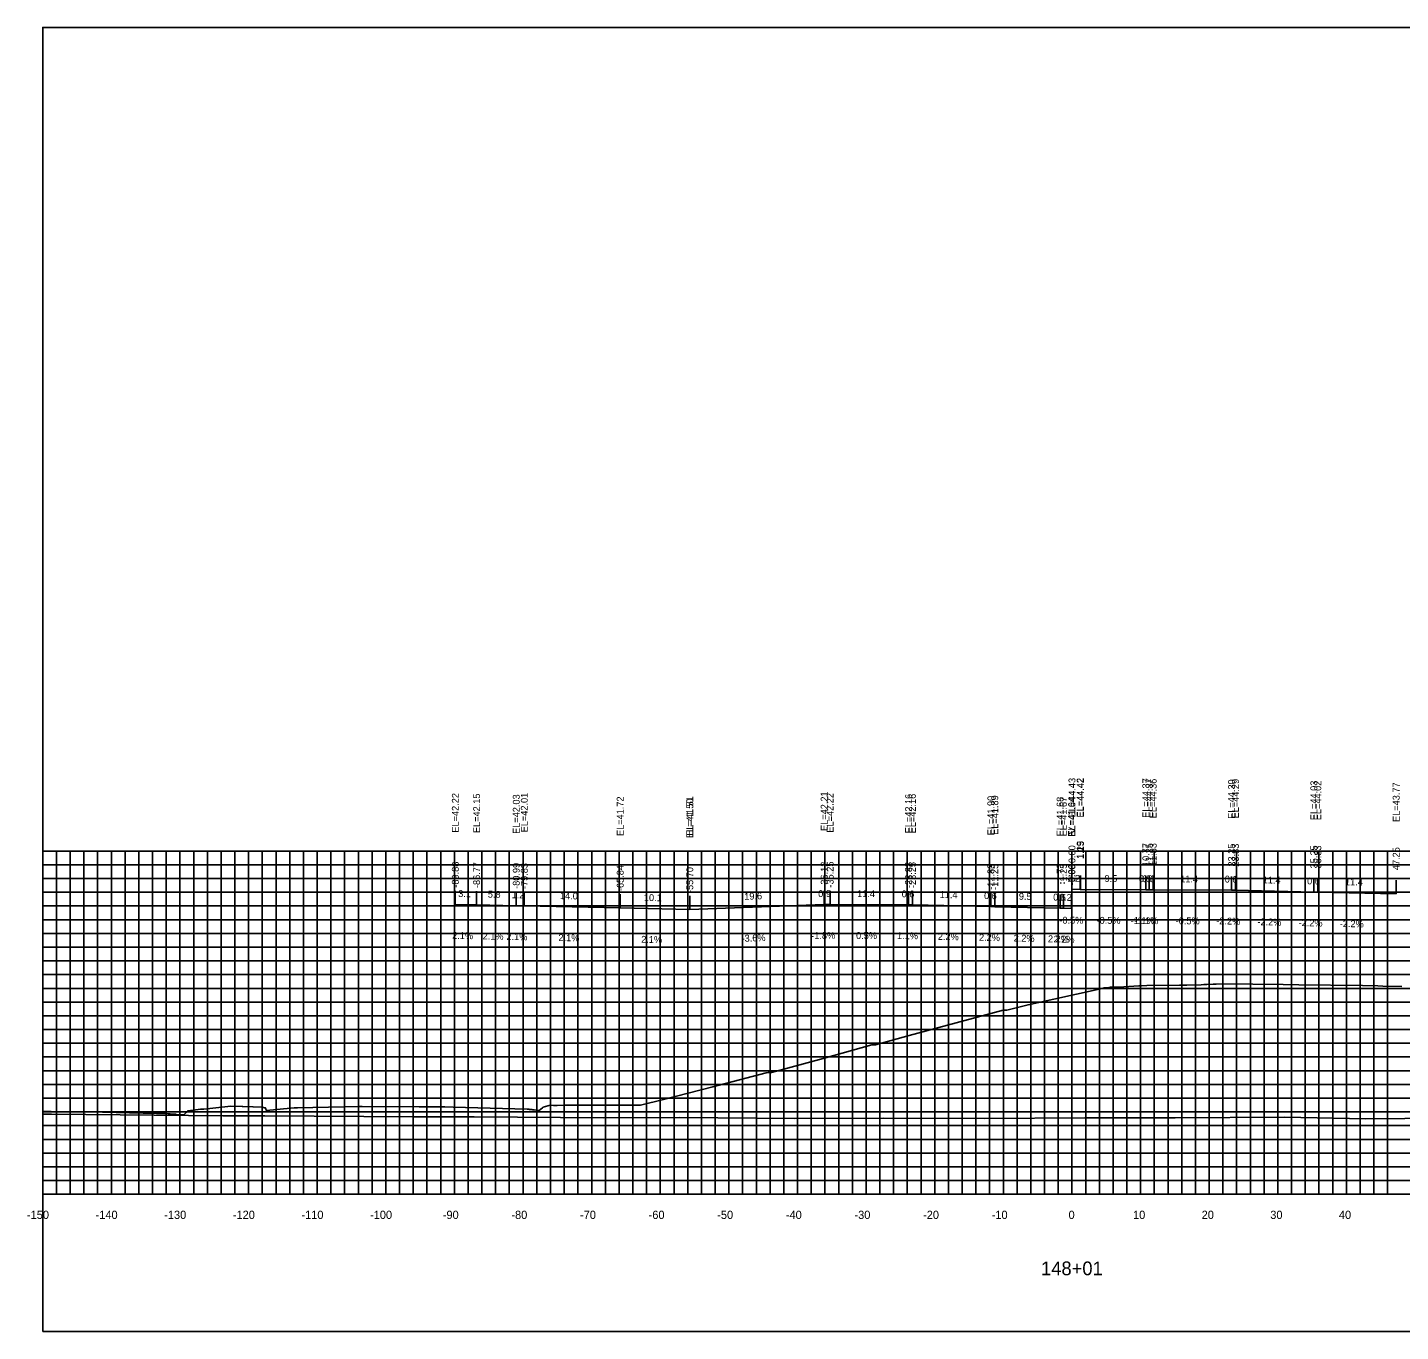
# Model space of a CAD drawing. Extents: x 1800880 to 1818864, y 245271 to 250560.
# Drawn here: x 1808044.3 to 1808244.4, y 246963.3 to 247153.3 of the extents above; entities that cross this region are included whole.
import ezdxf

# ---------------------------------------------------------------- set-up
doc = ezdxf.new("R2010")
doc.units = 0
for name, color, linetype in [('ANNO-TXT', 7, 'Continuous'), ('AXIS', 7, 'Continuous'), ('CL-CNST', 7, 'Continuous'), ('DESIGN - DRAINAGE - Bridges', 7, 'Continuous'), ('Level 32', 7, 'Continuous'), ('Level 37', 7, 'Continuous'), ('Level 46', 7, 'Continuous'), ('Level 62', 7, 'Continuous'), ('SHT-BDR', 7, 'Continuous')]:
    doc.layers.add(name, color=color, linetype=linetype)

msp = doc.modelspace()

# ---------------------------------------------------------------- linework, layer by layer
at = {"layer": 'AXIS'}
msp.add_lwpolyline([(1808196.5, 247027.72), (1808197.69, 247027.71), (1808197.75, 247027.71), (1808207.27, 247027.66), (1808207.75, 247027.65), (1808208.33, 247027.65), (1808219.75, 247027.59), (1808220.33, 247027.57), (1808231.75, 247027.32), (1808232.33, 247027.31), (1808243.75, 247027.06)], dxfattribs=at)
at = {"layer": 'CL-CNST'}
msp.add_lwpolyline([(1808046.5, 246995.34), (1808047.74, 246995.35), (1808051.34, 246995.31), (1808055.2, 246995.26), (1808063.09, 246995.07), (1808063.44, 246995.06), (1808063.82, 246995.05), (1808064.24, 246995.04), (1808064.32, 246995.03), (1808064.4, 246995.03), (1808064.78, 246995), (1808065.07, 246994.99), (1808065.29, 246994.97), (1808065.47, 246994.96), (1808065.61, 246994.95), (1808065.73, 246994.94), (1808065.84, 246994.94), (1808065.92, 246994.93), (1808067.06, 246994.86), (1808067.47, 246995.25), (1808067.6, 246995.35), (1808067.64, 246995.44), (1808067.68, 246995.44), (1808069.47, 246995.69), (1808069.83, 246995.69), (1808070, 246995.69), (1808073.91, 246996.12), (1808075.57, 246996.06), (1808075.66, 246996.06), (1808077.14, 246996.03), (1808077.18, 246996.02), (1808078.55, 246995.97), (1808078.65, 246995.92), (1808078.65, 246995.92), (1808078.66, 246995.92), (1808078.67, 246995.92), (1808078.67, 246995.92), (1808078.68, 246995.92), (1808078.69, 246995.92), (1808078.7, 246995.91), (1808078.71, 246995.91), (1808078.73, 246995.91), (1808078.74, 246995.91), (1808078.76, 246995.9), (1808078.78, 246995.9), (1808078.81, 246995.89), (1808078.84, 246995.89), (1808078.88, 246995.88), (1808078.92, 246995.87), (1808078.97, 246995.86), (1808078.98, 246995.83), (1808078.99, 246995.79), (1808078.99, 246995.76), (1808079, 246995.73), (1808079, 246995.71), (1808079.01, 246995.7), (1808079.1, 246995.51), (1808082.62, 246995.82), (1808082.67, 246995.83), (1808083.12, 246995.89), (1808083.32, 246995.89), (1808083.63, 246995.89), (1808090.37, 246996.02), (1808092.57, 246996.06), (1808093.05, 246996.06), (1808101.37, 246996.03), (1808105.09, 246996.02), (1808106.31, 246995.99), (1808117.1, 246995.7), (1808117.18, 246995.69), (1808117.33, 246995.67), (1808117.46, 246995.66), (1808117.57, 246995.64), (1808117.66, 246995.63), (1808117.74, 246995.63), (1808117.81, 246995.62), (1808117.87, 246995.61), (1808117.92, 246995.61), (1808117.97, 246995.6), (1808118.02, 246995.6), (1808118.06, 246995.59), (1808118.1, 246995.59), (1808118.14, 246995.59), (1808118.85, 246995.51), (1808119.31, 246995.88), (1808119.45, 246995.98), (1808120.43, 246996.25), (1808120.46, 246996.25), (1808120.51, 246996.25), (1808120.95, 246996.24), (1808121.46, 246996.24), (1808122.39, 246996.27), (1808133.1, 246996.28), (1808133.41, 246996.28), (1808133.6, 246996.28), (1808136.99, 246997.11), (1808144.15, 246998.95), (1808151.93, 247000.96), (1808152.25, 247001.03), (1808152.37, 247001.02), (1808152.69, 247001.01), (1808160.25, 247003.09), (1808167.35, 247005.05), (1808167.72, 247005.05), (1808167.85, 247005.05), (1808172.79, 247006.44), (1808186.45, 247010.09), (1808186.62, 247010.1), (1808187.03, 247010.11), (1808190.1, 247010.89), (1808200.88, 247013.28), (1808201.18, 247013.37), (1808201.87, 247013.42), (1808201.97, 247013.43), (1808202.13, 247013.44), (1808202.52, 247013.44), (1808202.76, 247013.45), (1808203.34, 247013.48), (1808206.24, 247013.64), (1808206.65, 247013.66), (1808207.42, 247013.71), (1808212.16, 247013.75), (1808213.22, 247013.76), (1808215.34, 247013.81), (1808215.74, 247013.83), (1808216.14, 247013.83), (1808217.07, 247013.89), (1808217.53, 247013.91), (1808218.42, 247013.96), (1808227.3, 247013.84), (1808229.55, 247013.81), (1808238.82, 247013.68), (1808241.09, 247013.65), (1808241.82, 247013.63), (1808244.59, 247013.56)], dxfattribs=at)
at = {"layer": 'DESIGN - DRAINAGE - Bridges'}
for p, q in [((1808046.44, 247033.29), (1808046.5, 247033.29)), ((1808046.5, 246983.29), (1808046.5, 247033.29)), ((1808046.44, 247023.29), (1808046.5, 247023.29)), ((1808046.44, 247013.29), (1808046.5, 247013.29)), ((1808046.44, 247003.29), (1808046.5, 247003.29)), ((1808046.44, 246993.29), (1808046.5, 246993.29)), ((1808046.44, 246983.29), (1808046.5, 246983.29)), ((1808046.5, 246983.29), (1808346.5, 246983.29)), ((1808046.5, 246983.23), (1808046.5, 246983.29)), ((1808056.5, 246983.23), (1808056.5, 246983.29)), ((1808066.5, 246983.23), (1808066.5, 246983.29)), ((1808076.5, 246983.23), (1808076.5, 246983.29)), ((1808086.5, 246983.23), (1808086.5, 246983.29)), ((1808096.5, 246983.23), (1808096.5, 246983.29)), ((1808106.5, 246983.23), (1808106.5, 246983.29)), ((1808116.5, 246983.23), (1808116.5, 246983.29)), ((1808126.5, 246983.23), (1808126.5, 246983.29)), ((1808136.5, 246983.23), (1808136.5, 246983.29)), ((1808146.5, 246983.23), (1808146.5, 246983.29)), ((1808156.5, 246983.23), (1808156.5, 246983.29)), ((1808166.5, 246983.23), (1808166.5, 246983.29)), ((1808176.5, 246983.23), (1808176.5, 246983.29)), ((1808186.5, 246983.23), (1808186.5, 246983.29)), ((1808196.5, 246983.23), (1808196.5, 246983.29)), ((1808206.5, 246983.23), (1808206.5, 246983.29)), ((1808216.5, 246983.23), (1808216.5, 246983.29)), ((1808226.5, 246983.23), (1808226.5, 246983.29)), ((1808236.5, 246983.23), (1808236.5, 246983.29))]:
    msp.add_line(p, q, dxfattribs=at)
at = {"layer": 'Level 37'}
for p, q in [((1808196.5, 247027.72), (1808196.5, 247029.72)), ((1808197.69, 247027.71), (1808197.69, 247029.71)), ((1808197.75, 247027.71), (1808197.75, 247029.71)), ((1808207.27, 247027.66), (1808207.27, 247029.66)), ((1808207.75, 247027.65), (1808207.75, 247029.65)), ((1808208.33, 247027.65), (1808208.33, 247029.65)), ((1808219.75, 247027.59), (1808219.75, 247029.59)), ((1808220.33, 247027.57), (1808220.33, 247029.57)), ((1808231.75, 247027.32), (1808231.75, 247029.32)), ((1808232.33, 247027.31), (1808232.33, 247029.31)), ((1808243.75, 247027.06), (1808243.75, 247029.06)), ((1808106.63, 247025.5), (1808106.63, 247027.5)), ((1808109.73, 247025.44), (1808109.73, 247027.44)), ((1808115.51, 247025.32), (1808115.51, 247027.32)), ((1808116.68, 247025.29), (1808116.68, 247027.29)), ((1808130.66, 247025), (1808130.66, 247027)), ((1808140.8, 247024.79), (1808140.8, 247026.79)), ((1808140.8, 247024.79), (1808140.8, 247026.79)), ((1808160.39, 247025.49), (1808160.39, 247027.49)), ((1808161.25, 247025.51), (1808161.25, 247027.51)), ((1808172.68, 247025.45), (1808172.68, 247027.45)), ((1808173.25, 247025.44), (1808173.25, 247027.44)), ((1808184.68, 247025.19), (1808184.68, 247027.19)), ((1808185.25, 247025.18), (1808185.25, 247027.18)), ((1808194.77, 247024.97), (1808194.77, 247026.97)), ((1808195.25, 247024.96), (1808195.25, 247026.96)), ((1808196.44, 247024.93), (1808196.44, 247026.93)), ((1808196.5, 247024.93), (1808196.5, 247026.93))]:
    msp.add_line(p, q, dxfattribs=at)
msp.add_lwpolyline([(1808046.5, 246963.29), (1808346.5, 246963.29), (1808346.5, 247153.29), (1808046.5, 247153.29)], close=True, dxfattribs=at)
at = {"layer": 'Level 46'}
for p, q in [((1808046.5, 247033.29), (1808346.5, 247033.29)), ((1808046.5, 246983.29), (1808046.5, 247033.29)), ((1808048.5, 246983.29), (1808048.5, 247033.29)), ((1808050.5, 246983.29), (1808050.5, 247033.29)), ((1808052.5, 246983.29), (1808052.5, 247033.29)), ((1808054.5, 246983.29), (1808054.5, 247033.29)), ((1808056.5, 246983.29), (1808056.5, 247033.29)), ((1808058.5, 246983.29), (1808058.5, 247033.29)), ((1808060.5, 246983.29), (1808060.5, 247033.29)), ((1808062.5, 246983.29), (1808062.5, 247033.29)), ((1808064.5, 246983.29), (1808064.5, 247033.29)), ((1808066.5, 246983.29), (1808066.5, 247033.29)), ((1808068.5, 246983.29), (1808068.5, 247033.29)), ((1808070.5, 246983.29), (1808070.5, 247033.29)), ((1808072.5, 246983.29), (1808072.5, 247033.29)), ((1808074.5, 246983.29), (1808074.5, 247033.29)), ((1808076.5, 246983.29), (1808076.5, 247033.29)), ((1808078.5, 246983.29), (1808078.5, 247033.29)), ((1808080.5, 246983.29), (1808080.5, 247033.29)), ((1808082.5, 246983.29), (1808082.5, 247033.29)), ((1808084.5, 246983.29), (1808084.5, 247033.29)), ((1808086.5, 246983.29), (1808086.5, 247033.29)), ((1808088.5, 246983.29), (1808088.5, 247033.29)), ((1808090.5, 246983.29), (1808090.5, 247033.29)), ((1808092.5, 246983.29), (1808092.5, 247033.29)), ((1808094.5, 246983.29), (1808094.5, 247033.29)), ((1808096.5, 246983.29), (1808096.5, 247033.29)), ((1808098.5, 246983.29), (1808098.5, 247033.29)), ((1808100.5, 246983.29), (1808100.5, 247033.29)), ((1808102.5, 246983.29), (1808102.5, 247033.29)), ((1808104.5, 246983.29), (1808104.5, 247033.29)), ((1808106.5, 246983.29), (1808106.5, 247033.29)), ((1808108.5, 246983.29), (1808108.5, 247033.29)), ((1808110.5, 246983.29), (1808110.5, 247033.29)), ((1808112.5, 246983.29), (1808112.5, 247033.29)), ((1808114.5, 246983.29), (1808114.5, 247033.29)), ((1808116.5, 246983.29), (1808116.5, 247033.29)), ((1808118.5, 246983.29), (1808118.5, 247033.29)), ((1808120.5, 246983.29), (1808120.5, 247033.29)), ((1808122.5, 246983.29), (1808122.5, 247033.29)), ((1808124.5, 246983.29), (1808124.5, 247033.29)), ((1808126.5, 246983.29), (1808126.5, 247033.29)), ((1808128.5, 246983.29), (1808128.5, 247033.29)), ((1808130.5, 246983.29), (1808130.5, 247033.29)), ((1808132.5, 246983.29), (1808132.5, 247033.29)), ((1808134.5, 246983.29), (1808134.5, 247033.29)), ((1808136.5, 246983.29), (1808136.5, 247033.29)), ((1808138.5, 246983.29), (1808138.5, 247033.29)), ((1808140.5, 246983.29), (1808140.5, 247033.29)), ((1808142.5, 246983.29), (1808142.5, 247033.29)), ((1808144.5, 246983.29), (1808144.5, 247033.29)), ((1808146.5, 246983.29), (1808146.5, 247033.29)), ((1808148.5, 246983.29), (1808148.5, 247033.29)), ((1808150.5, 246983.29), (1808150.5, 247033.29)), ((1808152.5, 246983.29), (1808152.5, 247033.29)), ((1808154.5, 246983.29), (1808154.5, 247033.29)), ((1808156.5, 246983.29), (1808156.5, 247033.29)), ((1808158.5, 246983.29), (1808158.5, 247033.29)), ((1808160.5, 246983.29), (1808160.5, 247033.29)), ((1808162.5, 246983.29), (1808162.5, 247033.29)), ((1808164.5, 246983.29), (1808164.5, 247033.29)), ((1808166.5, 246983.29), (1808166.5, 247033.29)), ((1808168.5, 246983.29), (1808168.5, 247033.29)), ((1808170.5, 246983.29), (1808170.5, 247033.29)), ((1808172.5, 246983.29), (1808172.5, 247033.29)), ((1808174.5, 246983.29), (1808174.5, 247033.29)), ((1808176.5, 246983.29), (1808176.5, 247033.29)), ((1808178.5, 246983.29), (1808178.5, 247033.29)), ((1808180.5, 246983.29), (1808180.5, 247033.29)), ((1808182.5, 246983.29), (1808182.5, 247033.29)), ((1808184.5, 246983.29), (1808184.5, 247033.29)), ((1808186.5, 246983.29), (1808186.5, 247033.29)), ((1808188.5, 246983.29), (1808188.5, 247033.29)), ((1808190.5, 246983.29), (1808190.5, 247033.29)), ((1808192.5, 246983.29), (1808192.5, 247033.29)), ((1808194.5, 246983.29), (1808194.5, 247033.29)), ((1808196.5, 246983.29), (1808196.5, 247033.29)), ((1808198.5, 246983.29), (1808198.5, 247033.29)), ((1808200.5, 246983.29), (1808200.5, 247033.29)), ((1808202.5, 246983.29), (1808202.5, 247033.29)), ((1808204.5, 246983.29), (1808204.5, 247033.29)), ((1808206.5, 246983.29), (1808206.5, 247033.29)), ((1808208.5, 246983.29), (1808208.5, 247033.29)), ((1808210.5, 246983.29), (1808210.5, 247033.29)), ((1808212.5, 246983.29), (1808212.5, 247033.29)), ((1808214.5, 246983.29), (1808214.5, 247033.29)), ((1808216.5, 246983.29), (1808216.5, 247033.29)), ((1808218.5, 246983.29), (1808218.5, 247033.29)), ((1808220.5, 246983.29), (1808220.5, 247033.29)), ((1808222.5, 246983.29), (1808222.5, 247033.29)), ((1808224.5, 246983.29), (1808224.5, 247033.29)), ((1808226.5, 246983.29), (1808226.5, 247033.29)), ((1808228.5, 246983.29), (1808228.5, 247033.29)), ((1808230.5, 246983.29), (1808230.5, 247033.29)), ((1808232.5, 246983.29), (1808232.5, 247033.29)), ((1808234.5, 246983.29), (1808234.5, 247033.29)), ((1808236.5, 246983.29), (1808236.5, 247033.29)), ((1808238.5, 246983.29), (1808238.5, 247033.29)), ((1808240.5, 246983.29), (1808240.5, 247033.29)), ((1808242.5, 246983.29), (1808242.5, 247033.29)), ((1808046.5, 247031.29), (1808346.5, 247031.29)), ((1808046.5, 247029.29), (1808346.5, 247029.29)), ((1808046.5, 247027.29), (1808346.5, 247027.29)), ((1808046.5, 247025.29), (1808346.5, 247025.29)), ((1808046.5, 247023.29), (1808346.5, 247023.29)), ((1808046.5, 247021.29), (1808346.5, 247021.29)), ((1808046.5, 247019.29), (1808346.5, 247019.29)), ((1808046.5, 247017.29), (1808346.5, 247017.29)), ((1808046.5, 247015.29), (1808346.5, 247015.29)), ((1808046.5, 247013.29), (1808346.5, 247013.29)), ((1808046.5, 247011.29), (1808346.5, 247011.29)), ((1808046.5, 247009.29), (1808346.5, 247009.29)), ((1808046.5, 247007.29), (1808346.5, 247007.29)), ((1808046.5, 247005.29), (1808346.5, 247005.29)), ((1808046.5, 247003.29), (1808346.5, 247003.29)), ((1808046.5, 247001.29), (1808346.5, 247001.29)), ((1808046.5, 246999.29), (1808346.5, 246999.29)), ((1808046.5, 246997.29), (1808346.5, 246997.29)), ((1808046.5, 246995.29), (1808346.5, 246995.29)), ((1808046.5, 246993.29), (1808346.5, 246993.29)), ((1808046.5, 246991.29), (1808346.5, 246991.29)), ((1808046.5, 246989.29), (1808346.5, 246989.29)), ((1808046.5, 246987.29), (1808346.5, 246987.29)), ((1808046.5, 246985.29), (1808346.5, 246985.29)), ((1808046.5, 246983.29), (1808346.5, 246983.29))]:
    msp.add_line(p, q, dxfattribs=at)
at = {"layer": 'Level 62'}
for points in [[(1808106.63, 247025.5), (1808109.73, 247025.44), (1808115.51, 247025.32), (1808116.68, 247025.29), (1808130.66, 247025), (1808140.8, 247024.79)], [(1808140.8, 247024.79), (1808160.39, 247025.49), (1808161.25, 247025.51), (1808172.68, 247025.45), (1808173.25, 247025.44), (1808184.68, 247025.19), (1808185.25, 247025.18), (1808194.77, 247024.97), (1808195.25, 247024.96), (1808196.44, 247024.93), (1808196.5, 247024.93)], [(1808046.5, 246994.96), (1808047.77, 246994.95), (1808072.75, 246994.72), (1808078.89, 246994.71), (1808100.5, 246994.57), (1808109.36, 246994.57), (1808128.26, 246994.44), (1808139.37, 246994.45), (1808156.02, 246994.34), (1808169.02, 246994.38), (1808183.77, 246994.33), (1808198.39, 246994.4), (1808211.53, 246994.42), (1808227.54, 246994.51), (1808239.28, 246994.3), (1808256.52, 246994.4), (1808267.04, 246994.52), (1808276.74, 246994.45), (1808294.79, 246994.56), (1808304.21, 246994.72), (1808322.55, 246994.83), (1808331.64, 246994.58), (1808346.5, 246994.68)]]:
    msp.add_lwpolyline(points, dxfattribs=at)

# ---------------------------------------------------------------- texts
for s, p in [('-150', (1808044.2, 246979.69)), ('-140', (1808054.2, 246979.69)), ('-130', (1808064.2, 246979.69)), ('-120', (1808074.2, 246979.69)), ('-110', (1808084.2, 246979.69)), ('-100', (1808094.2, 246979.69)), ('-90', (1808104.8, 246979.69)), ('-80', (1808114.8, 246979.69)), ('-70', (1808124.8, 246979.69)), ('-60', (1808134.8, 246979.69)), ('-50', (1808144.8, 246979.69)), ('-40', (1808154.8, 246979.69)), ('-30', (1808164.8, 246979.69)), ('-20', (1808174.8, 246979.69)), ('-10', (1808184.8, 246979.69)), ('0', (1808196, 246979.69)), ('10', (1808205.4, 246979.69)), ('20', (1808215.4, 246979.69)), ('30', (1808225.4, 246979.69)), ('40', (1808235.4, 246979.69))]:
    msp.add_text(s, height=1.2).set_placement(p)
at = {"layer": 'ANNO-TXT'}
for s, rotation, p in [('1.2', 359.6981, (1808195.82, 247028.82)), ('9.5', 359.6981, (1808201.24, 247028.79)), ('0.5', 359.3576, (1808206.24, 247028.77)), ('0.6', 359.3576, (1808206.75, 247028.76)), ('11.4', 359.6981, (1808212.27, 247028.73)), ('0.6', 358.7397, (1808218.76, 247028.71)), ('11.4', 358.7397, (1808224.29, 247028.59)), ('0.6', 358.7397, (1808230.76, 247028.44)), ('11.4', 358.7397, (1808236.29, 247028.32)), ('3.1', 358.8131, (1808107.04, 247026.6)), ('5.8', 358.8087, (1808111.36, 247026.51)), ('1.2', 358.8087, (1808114.83, 247026.43)), ('14.0', 358.8087, (1808121.87, 247026.29)), ('10.1', 358.8087, (1808134.1, 247026.03)), ('19.6', 2.0532, (1808148.75, 247026.18)), ('0.9', 1.0364, (1808159.52, 247026.58)), ('11.4', 359.6981, (1808165.19, 247026.59)), ('0.6', 359.3576, (1808171.67, 247026.56)), ('11.4', 358.7397, (1808177.21, 247026.46)), ('0.6', 358.7397, (1808183.68, 247026.31)), ('9.5', 358.7397, (1808188.75, 247026.2)), ('0.5', 358.7397, (1808193.75, 247026.09)), ('1.2', 358.7397, (1808194.59, 247026.07)), ('-0.5%', 359.6981, (1808194.66, 247022.72)), ('-0.5%', 359.6981, (1808200.08, 247022.7)), ('-1.1%', 359.3576, (1808205.05, 247022.68)), ('-1.1%', 359.3576, (1808205.58, 247022.68)), ('-0.5%', 359.6981, (1808211.61, 247022.63)), ('-2.2%', 358.7397, (1808217.52, 247022.63)), ('-2.2%', 358.7397, (1808223.52, 247022.5)), ('-2.2%', 358.7397, (1808229.52, 247022.37)), ('-2.2%', 358.7397, (1808235.52, 247022.24)), ('2.1%', 358.8131, (1808106.16, 247020.51)), ('2.1%', 358.8087, (1808110.6, 247020.42)), ('2.1%', 358.8087, (1808114.08, 247020.35)), ('2.1%', 358.8087, (1808121.65, 247020.19)), ('2.1%', 358.8087, (1808133.71, 247019.94)), ('-3.6%', 2.0532, (1808148.36, 247020.06)), ('-1.8%', 1.0364, (1808158.5, 247020.46)), ('0.5%', 359.6981, (1808165.03, 247020.49)), ('1.1%', 359.3576, (1808171, 247020.47)), ('2.2%', 358.7397, (1808176.94, 247020.36)), ('2.2%', 358.7397, (1808182.94, 247020.23)), ('2.2%', 358.7397, (1808187.99, 247020.12)), ('2.2%', 358.7397, (1808192.99, 247020.01)), ('2.2%', 358.7397, (1808193.82, 247019.99))]:
    msp.add_text(s, height=1, rotation=rotation, dxfattribs=at).set_placement(p)
at = {"layer": 'DESIGN - DRAINAGE - Bridges'}
for s, height, p in [('>', 1.5, (1808195.9, 247035.54)), ('-', 0.0001, (1808046.5, 246983.29))]:
    msp.add_text(s, height=height, dxfattribs=at).set_placement(p)
at = {"layer": 'Level 32'}
msp.add_text('148+01', height=2, dxfattribs=at).set_placement((1808191.99, 246971.49))
at = {"layer": 'SHT-BDR'}
for s, p in [('EL=44.43', (1808197, 247038.19)), ('EL=44.42', (1808198.19, 247038.18)), ('EL=44.42', (1808198.25, 247038.18)), ('EL=44.37', (1808207.77, 247038.13)), ('EL=44.37', (1808208.25, 247038.13)), ('EL=44.36', (1808208.83, 247038.07)), ('EL=44.30', (1808220.25, 247037.98)), ('EL=44.29', (1808220.83, 247038.05)), ('EL=44.03', (1808232.25, 247037.79)), ('EL=44.02', (1808232.83, 247037.78)), ('EL=43.77', (1808244.25, 247037.53)), ('EL=42.22', (1808107.13, 247035.98)), ('EL=42.15', (1808110.23, 247035.91)), ('EL=42.03', (1808116.01, 247035.79)), ('EL=42.01', (1808117.18, 247036.02)), ('EL=41.72', (1808131.16, 247035.48)), ('EL=41.50', (1808141.3, 247035.18)), ('EL=41.51', (1808141.3, 247035.52)), ('EL=42.21', (1808160.89, 247036.22)), ('EL=42.22', (1808161.75, 247035.98)), ('EL=42.16', (1808173.18, 247035.87)), ('EL=42.16', (1808173.75, 247035.87)), ('EL=41.90', (1808185.18, 247035.58)), ('EL=41.89', (1808185.75, 247035.65)), ('EL=41.68', (1808195.27, 247035.44)), ('EL=41.67', (1808195.75, 247035.43)), ('EL=41.64', (1808196.94, 247035.4)), ('EL=41.64', (1808197, 247035.4)), ('1.19', (1808198.19, 247032.15)), ('1.25', (1808198.25, 247032.15)), ('-0.00', (1808197, 247031.09)), ('10.77', (1808207.77, 247031.11)), ('11.25', (1808208.25, 247031.1)), ('11.83', (1808208.83, 247031.1)), ('23.25', (1808220.25, 247031.03)), ('23.83', (1808220.83, 247031.02)), ('35.25', (1808232.25, 247030.77)), ('35.83', (1808232.83, 247030.76)), ('47.25', (1808244.25, 247030.51)), ('-89.88', (1808107.13, 247027.96)), ('-86.77', (1808110.23, 247027.9)), ('-80.99', (1808116.01, 247027.78)), ('-79.83', (1808117.18, 247027.75)), ('-65.84', (1808131.16, 247027.46)), ('-55.70', (1808141.3, 247027.17)), ('-55.70', (1808141.3, 247027.17)), ('-36.12', (1808160.89, 247027.95)), ('-35.25', (1808161.75, 247027.97)), ('-23.83', (1808173.18, 247027.91)), ('-23.25', (1808173.75, 247027.9)), ('-11.83', (1808185.18, 247027.65)), ('-11.25', (1808185.75, 247027.63)), ('-1.73', (1808195.27, 247028.42)), ('-1.25', (1808195.75, 247028.41)), ('-0.06', (1808196.94, 247028.33)), ('-0.00', (1808197, 247028.3))]:
    msp.add_text(s, height=1, rotation=90, dxfattribs=at).set_placement(p)

doc.saveas('drawing.dxf')
